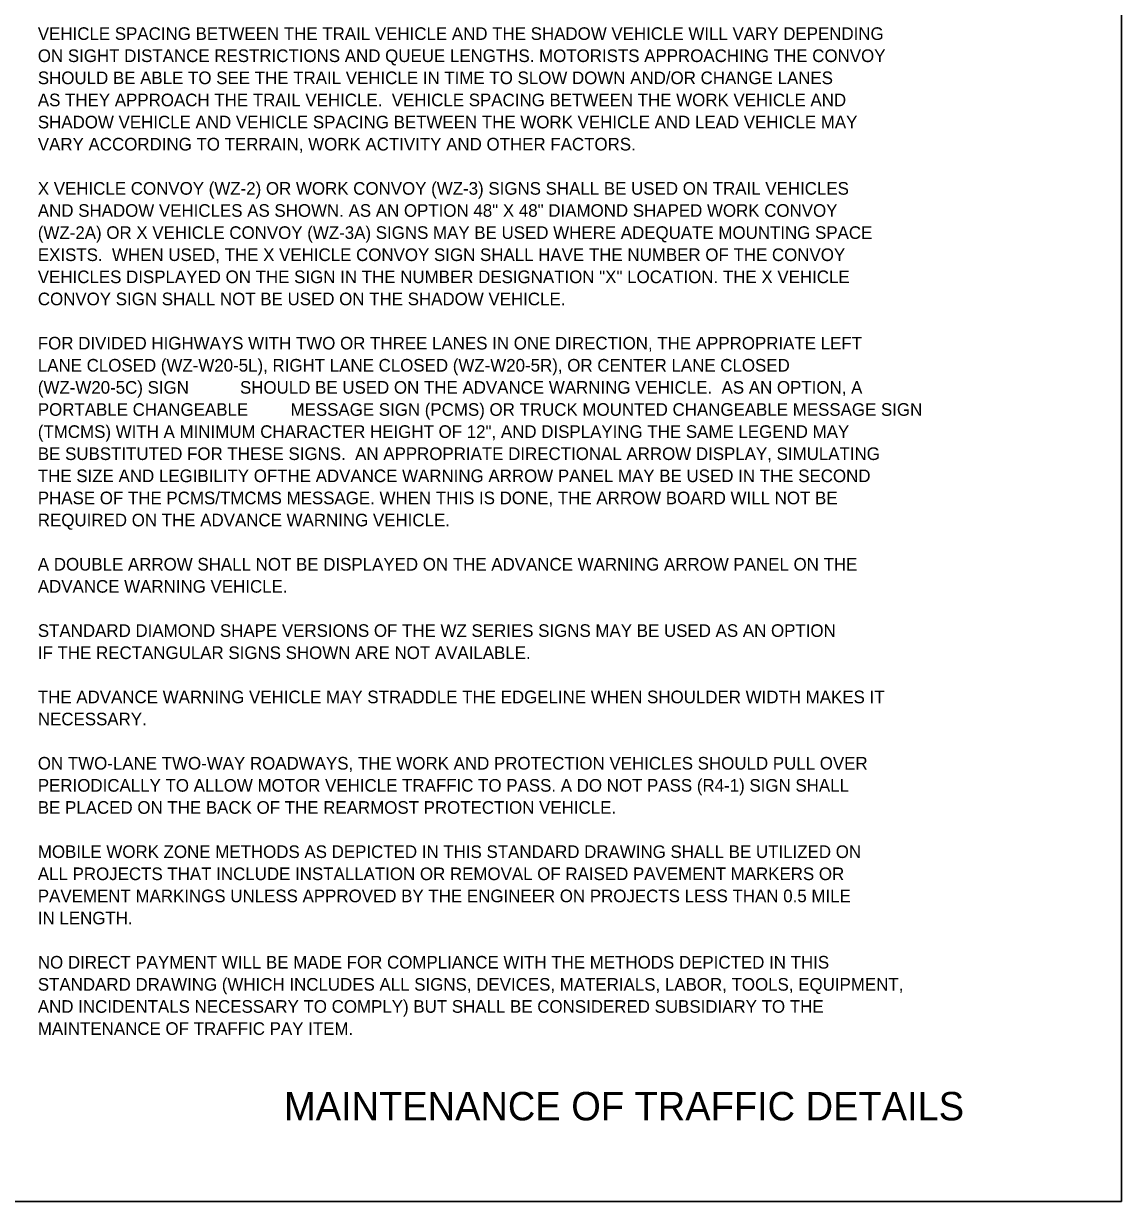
# Model space of a CAD drawing. Extents: x 1374027 to 1374537, y 380415 to 381405.
# Drawn here: x 1374144.9 to 1374197.1, y 381295.2 to 381351.1 of the extents above; entities that cross this region are included whole.
import ezdxf

# ---------------------------------------------------------------- set-up
doc = ezdxf.new("R2010")
doc.units = 0
for name, color, linetype in [('DSN_DRFT_Junk-No-Plot', 7, 'Continuous'), ('R_Border Notes', 7, 'Continuous'), ('Working Level 1', 7, 'Continuous')]:
    doc.layers.add(name, color=color, linetype=linetype)

msp = doc.modelspace()

# ---------------------------------------------------------------- linework, layer by layer
at = {"layer": 'DSN_DRFT_Junk-No-Plot'}
for points in [[(1374027.083, 381405.174), (1374197.083, 381405.174), (1374197.083, 381295.174), (1374027.083, 381295.174)], [(1374027.083, 381405.174), (1374027.083, 381295.174), (1374197.083, 381295.174), (1374197.083, 381405.174)]]:
    msp.add_lwpolyline(points, close=True, dxfattribs=at)

# ---------------------------------------------------------------- texts
at = {"layer": 'R_Border Notes'}
msp.add_text('MAINTENANCE OF TRAFFIC DETAILS', height=1.35, dxfattribs=at).set_placement((1374157.313, 381299.024))
at = {"layer": 'Working Level 1'}
for s, p in [('VEHICLE SPACING BETWEEN THE TRAIL VEHICLE AND THE SHADOW VEHICLE WILL VARY DEPENDING ', (1374145.622, 381350.333)), ('ON SIGHT DISTANCE RESTRICTIONS AND QUEUE LENGTHS. MOTORISTS APPROACHING THE CONVOY ', (1374145.622, 381349.283)), ('SHOULD BE ABLE TO SEE THE TRAIL VEHICLE IN TIME TO SLOW DOWN AND/OR CHANGE LANES ', (1374145.622, 381348.233)), ('AS THEY APPROACH THE TRAIL VEHICLE.  VEHICLE SPACING BETWEEN THE WORK VEHICLE AND ', (1374145.622, 381347.183)), ('SHADOW VEHICLE AND VEHICLE SPACING BETWEEN THE WORK VEHICLE AND LEAD VEHICLE MAY ', (1374145.622, 381346.133)), ('VARY ACCORDING TO TERRAIN, WORK ACTIVITY AND OTHER FACTORS.', (1374145.622, 381345.083)), ('X VEHICLE CONVOY (WZ-2) OR WORK CONVOY (WZ-3) SIGNS SHALL BE USED ON TRAIL VEHICLES', (1374145.622, 381342.983)), ('AND SHADOW VEHICLES AS SHOWN. AS AN OPTION 48" X 48" DIAMOND SHAPED WORK CONVOY', (1374145.622, 381341.933)), ('(WZ-2A) OR X VEHICLE CONVOY (WZ-3A) SIGNS MAY BE USED WHERE ADEQUATE MOUNTING SPACE', (1374145.622, 381340.883)), ('EXISTS.  WHEN USED, THE X VEHICLE CONVOY SIGN SHALL HAVE THE NUMBER OF THE CONVOY', (1374145.622, 381339.833)), ('VEHICLES DISPLAYED ON THE SIGN IN THE NUMBER DESIGNATION "X" LOCATION. THE X VEHICLE', (1374145.622, 381338.783)), ('CONVOY SIGN SHALL NOT BE USED ON THE SHADOW VEHICLE.', (1374145.622, 381337.733)), ('FOR DIVIDED HIGHWAYS WITH TWO OR THREE LANES IN ONE DIRECTION, THE APPROPRIATE LEFT ', (1374145.622, 381335.633)), ('LANE CLOSED (WZ-W20-5L), RIGHT LANE CLOSED (WZ-W20-5R), OR CENTER LANE CLOSED ', (1374145.622, 381334.583)), ('(WZ-W20-5C) SIGN', (1374145.622, 381333.533)), ('SHOULD BE USED ON THE ADVANCE WARNING VEHICLE.  AS AN OPTION, A ', (1374155.222, 381333.533)), ('PORTABLE CHANGEABLE', (1374145.622, 381332.483)), ('MESSAGE SIGN (PCMS) OR TRUCK MOUNTED CHANGEABLE MESSAGE SIGN ', (1374157.622, 381332.483)), ('(TMCMS) WITH A MINIMUM CHARACTER HEIGHT OF 12", AND DISPLAYING THE SAME LEGEND MAY ', (1374145.622, 381331.433)), ('BE SUBSTITUTED FOR THESE SIGNS.  AN APPROPRIATE DIRECTIONAL ARROW DISPLAY, SIMULATING ', (1374145.622, 381330.383)), ('THE SIZE AND LEGIBILITY OFTHE ADVANCE WARNING ARROW PANEL MAY BE USED IN THE SECOND ', (1374145.622, 381329.333)), ('PHASE OF THE PCMS/TMCMS MESSAGE. WHEN THIS IS DONE, THE ARROW BOARD WILL NOT BE ', (1374145.622, 381328.283)), ('REQUIRED ON THE ADVANCE WARNING VEHICLE.', (1374145.622, 381327.233)), ('A DOUBLE ARROW SHALL NOT BE DISPLAYED ON THE ADVANCE WARNING ARROW PANEL ON THE ', (1374145.622, 381325.133)), ('ADVANCE WARNING VEHICLE. ', (1374145.622, 381324.083)), ('STANDARD DIAMOND SHAPE VERSIONS OF THE WZ SERIES SIGNS MAY BE USED AS AN OPTION ', (1374145.622, 381321.983)), ('IF THE RECTANGULAR SIGNS SHOWN ARE NOT AVAILABLE.', (1374145.622, 381320.933)), ('THE ADVANCE WARNING VEHICLE MAY STRADDLE THE EDGELINE WHEN SHOULDER WIDTH MAKES IT ', (1374145.622, 381318.833)), ('NECESSARY.', (1374145.622, 381317.783)), ('ON TWO-LANE TWO-WAY ROADWAYS, THE WORK AND PROTECTION VEHICLES SHOULD PULL OVER', (1374145.622, 381315.683)), ('PERIODICALLY TO ALLOW MOTOR VEHICLE TRAFFIC TO PASS. A DO NOT PASS (R4-1) SIGN SHALL ', (1374145.622, 381314.633)), ('BE PLACED ON THE BACK OF THE REARMOST PROTECTION VEHICLE.', (1374145.622, 381313.583)), ('MOBILE WORK ZONE METHODS AS DEPICTED IN THIS STANDARD DRAWING SHALL BE UTILIZED ON ', (1374145.622, 381311.483)), ('ALL PROJECTS THAT INCLUDE INSTALLATION OR REMOVAL OF RAISED PAVEMENT MARKERS OR ', (1374145.622, 381310.433)), ('PAVEMENT MARKINGS UNLESS APPROVED BY THE ENGINEER ON PROJECTS LESS THAN 0.5 MILE ', (1374145.622, 381309.383)), ('IN LENGTH.', (1374145.622, 381308.333)), ('NO DIRECT PAYMENT WILL BE MADE FOR COMPLIANCE WITH THE METHODS DEPICTED IN THIS ', (1374145.622, 381306.233)), ('STANDARD DRAWING (WHICH INCLUDES ALL SIGNS, DEVICES, MATERIALS, LABOR, TOOLS, EQUIPMENT, ', (1374145.622, 381305.183)), ('AND INCIDENTALS NECESSARY TO COMPLY) BUT SHALL BE CONSIDERED SUBSIDIARY TO THE ', (1374145.622, 381304.133)), ('MAINTENANCE OF TRAFFIC PAY ITEM.', (1374145.622, 381303.083))]:
    msp.add_text(s, height=0.6, dxfattribs=at).set_placement(p)

doc.saveas('drawing.dxf')
